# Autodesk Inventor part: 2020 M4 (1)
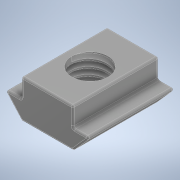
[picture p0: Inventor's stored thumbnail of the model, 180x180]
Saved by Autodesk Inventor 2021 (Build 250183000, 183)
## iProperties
Created: 2026-01
Part Number: 2020 M4 (1)
Material: Generic
Description: STEP AP214
Document SubType Name: Modeling
Designer: hp
Density: 1 g/cm^3
Appearance: Default
Sending System: SolidWorks 2020
Preprocessor: SwSTEP 2.0
Title: T-Slot Somunu.STEP
Revision Number: HERHANGÝ
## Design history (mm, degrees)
feature "Radyus1"
body "Solid1"
